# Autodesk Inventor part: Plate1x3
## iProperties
Created: 2006-02
Part Number: Plate1x3
Material: Stainless Steel
Document SubType Name: Modeling
Designer: 40664
Mass: 267852 g
Surface Area: 67075 cm^2
Volume: 33150 cm^3
Density: 8.08 g/cm^3
CSToolsMass: 268.0
CSToolsVolume: 33150000.0
CSToolsArea: 67075.0
Author: 40664
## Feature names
1. Extrusion2
